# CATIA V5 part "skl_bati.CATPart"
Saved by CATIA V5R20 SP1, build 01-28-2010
Part number: skl_bati
Publications: "Droite.1", "Droite.2", "Droite.3", "Droite.4", "Droite.5", "Plan xy"
Bounding box of the stored display mesh (mm): x 0 to 668.11, y 0 to 1006.613, z 0 to 100
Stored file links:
  C:\Users\Manon\Desktop\IAO\SKL_rlanglais\skl_bati.CATPart
  C:\Users\Manon\Desktop\IAO\SKL_rlanglais\SKL_rlanglais.CATProduct
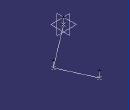
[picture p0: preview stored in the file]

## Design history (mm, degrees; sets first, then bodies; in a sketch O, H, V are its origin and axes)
Set1
  Point1 "G": linked copy from another document
  Point2 "D": linked copy from another document
  Point3 "A": linked copy from another document
Set2
  Line1: type PtPt, FirstPoint Point1, SecondPoint Point2
  Line2: type PtPt, FirstPoint Point2, SecondPoint Point3
  Line3: type Normal, RefPoint Point1, RefSkin xy-plane, Start 0, End 100
  Line4: type Normal, RefPoint Point2, RefSkin xy-plane, Start 0, End 100
  Line5: type Normal, RefPoint Point3, RefSkin xy-plane, Start 0, End 100
Body1 (main body)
